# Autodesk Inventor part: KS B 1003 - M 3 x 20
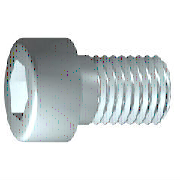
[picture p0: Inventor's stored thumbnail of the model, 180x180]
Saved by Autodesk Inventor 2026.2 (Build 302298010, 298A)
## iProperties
Created: 2025-01
Part Number: KS B 1003 - M 3 x 20
Material: 강철, 연강
Description: 6각머리 태핑 나사
Document SubType Name: Modeling
Standard: KS B 1003
Designer: work
Standards Organization: KS
Language: ko-KR
Size Designation: M 3 x 20
Categories: <MemberInstance><Categories><Category DisplayName="조임쇠" InternalName="e4da775c-781d-43d5-af7c-5136215cf5a6" Mnemonic="FSTN"><Category DisplayName="볼트" InternalN
Density: 7.85 g/cm^3
Appearance: 반연마
IsCustomPart: 1
Author: work
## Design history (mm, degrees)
body "Solid1"
workplane "Work Plane1"
fillet "Fillet2" dims "d30" = 0.1 (= R)
revolve "본체" stored, may be unused: angle "d10" = 90 deg
sketch "스케치2"
  geometry: L1 (0, -3.85)-(0, 3.85) reference; L2 (-3.85, 0)-(3.85, 0) reference; L3 (1.443, 0)-(0.722, -1.25); L4 (0.722, -1.25)-(-0.722, -1.25); L5 (-0.722, -1.25)-(-1.443, 0); L6 (-1.443, 0)-(-0.722, 1.25); L7 (-0.722, 1.25)-(0.722, 1.25); L8 (0.722, 1.25)-(1.443, 0); 2 further points
  constraints: 12 end point, 1 coincident, 1 horizontal alignment, 1 point on line, 12 other
extrude "슬롯" join sketch "스케치2" stored distance "d11" = 10; taper "d12" = 0 deg
fillet "모깎기1" dims "d17" = 0.3 (= RR)
feature "스레드" dims "d13" = 18.75 (= GEL), "d14" = 0
chamfer "모따기1" distance "d15" = 0.30673 (= -0.5 x SPD + 0.5 x GD); stored, may be unused: second distance "d16" = 0.30673 (= GUL), angle "d27" = 45 deg
sketch "스케치1"
  geometry: L1 (-0.867, 0)-(20, 0); L2 (20, 0)-(20, 1.5); L3 (20, 1.5)-(1.25, 1.5); L4 (1.25, 1.5)-(0.943, 1.5); L5 (0.943, 1.5)-(0, 1.5); L6 (0, 1.5)-(0, 2.75); L7 (0, 2.75)-(-3, 2.75); L8 (-3, 2.75)-(-3, 1.443); L9 (-3, 1.443)-(-1.7, 1.443); L10 (-1.7, 1.443)-(-0.867, 0); L11 (-7.6, 0)-(24.6, 0) reference; L12 (0, -0.55)-(0, 3.3) reference; L13 (1.25, 1.5)-(0, 1.5)
  constraints: 22 end point, 6 parallel, 2 collinear, 2 perpendicular, 1 horizontal, 1 point on line
  dimensions: "d1" = 18.75 distance from line of L3.end L2 (= GEL); "d2" = 0.30683 distance of L4.end L3.end (computed from GAL); "d3" = 3 distance between parallel lines of L8 L6 (= KOH); "d4" = 1.3 distance of L8.end L9.end (= INTI); "d5" = 60 deg angle of L10 L1; "d6" = 3 diameter of L3 L1 (= GD); "d7" = 3 diameter of L5 L1 (= BDM); "d8" = 2.88675 diameter of L9 L1 (= 1.1547 x SW); "d9" = 5.5 diameter of L7 L1 (= KOD); "d26" = 20 distance between parallel lines of L12 L2 (= NLG)
other parameters: "GD" = 3 (= NND) [user parameter; used in 2 equation terms], "NLG" = 20 [user parameter; used in 1 equation term], "GEL" = 18.75 [user parameter; used in 2 equation terms], "KOD" = 5.5 [user parameter; used in 1 equation term], "KOH" = 3 [user parameter; used in 1 equation term], "INTI" = 1.3 [user parameter; used in 1 equation term], "GAL" = 0.30673 (= 0.61345 x PTC) [user parameter; used in 1 equation term], "GUL" = 0.30673 (= 0.61345 x PTC) [user parameter; used in 1 equation term], "BDM" = 3 (= NND) [user parameter; used in 1 equation term], "SW" = 2.5 [user parameter; used in 2 equation terms], "RR" = 0.3 [user parameter; used in 1 equation term], "SPD" = 2.38655 (= NND - 1.2269 x PTC) [user parameter; used in 1 equation term], "d19" = 0, "d28" = 0, "d29" = 0, "R" = 0.1 [user parameter; used in 1 equation term], "PHH" = 0.1 [user parameter], "GD1" = 2.38655 (= THREADDIA - 1.2269 x PTC) [user parameter], "THREADDIA" = 3 [user parameter; used in 1 equation term], "FAWI" = 45 deg [user parameter], "PTC" = 0.5 [user parameter; used in 5 equation terms], "NND" = 3 [user parameter; used in 3 equation terms], "TOA" = 30 deg [user parameter], "E0" = 2.8875 (= 1.155 x SW) [user parameter]
